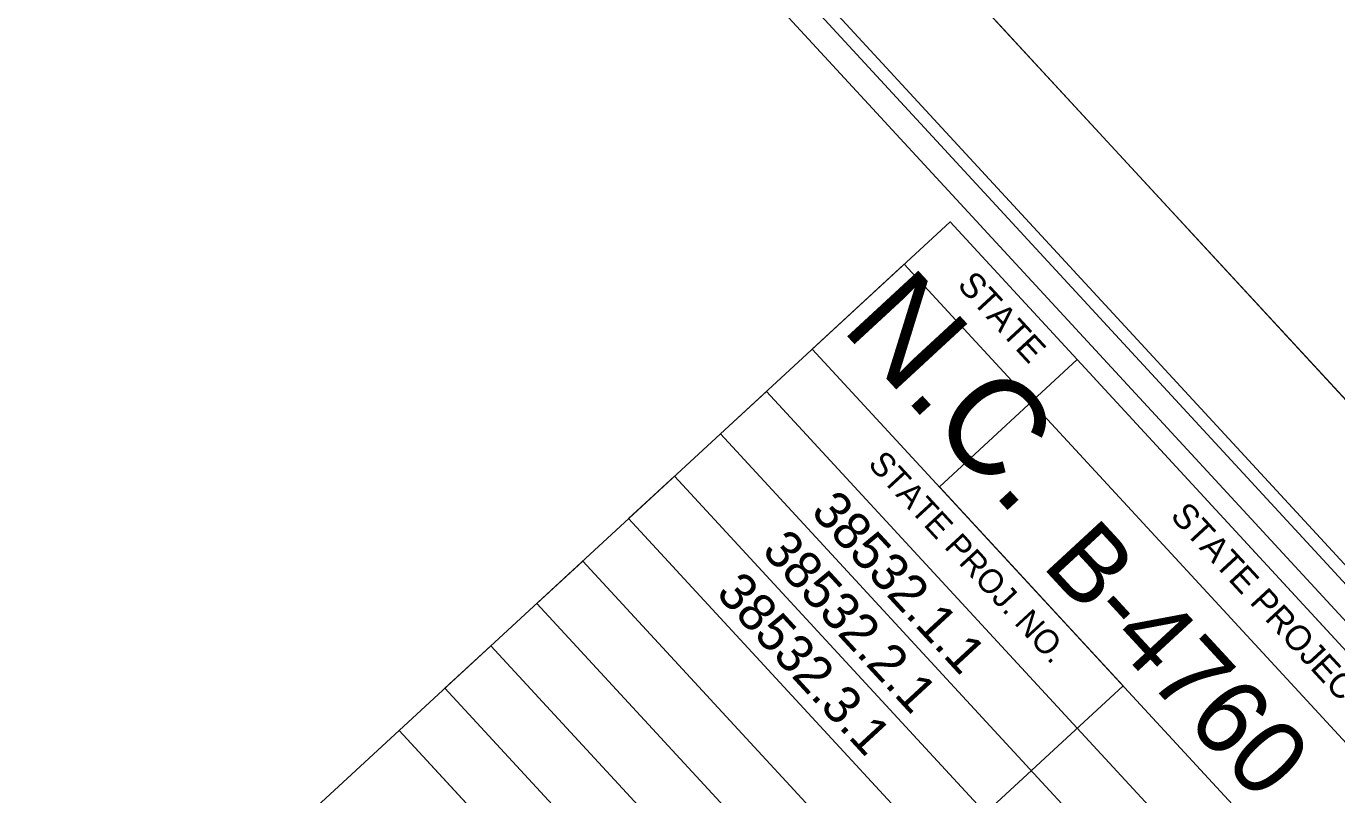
# Model space of a CAD drawing. Extents: x 1695041 to 1706254, y 786537 to 798223.
# Drawn here: x 1705012 to 1705798, y 794761 to 795222 of the extents above; entities that cross this region are included whole.
import ezdxf

# ---------------------------------------------------------------- set-up
doc = ezdxf.new("R2010")
doc.units = 0
for name, color, linetype in [('Old_Level_12', 7, 'Continuous'), ('Sheet Cutting Line CELL', 7, 'Continuous'), ('Sheet Data Field CELL', 7, 'Continuous'), ('Sheet Plot Border Inside CELL', 7, 'Continuous'), ('Sheet Plot Border Outside CELL', 7, 'Continuous'), ('Sheet Title CELL', 7, 'Continuous')]:
    doc.layers.add(name, color=color, linetype=linetype)

msp = doc.modelspace()

# ---------------------------------------------------------------- linework, layer by layer
at = {"layer": 'Old_Level_12'}
msp.add_lwpolyline([(1705795.09, 794193.47), (1705235.51, 794799.69), (1705053.77, 794631.93), (1705613.35, 794025.71)], close=True, dxfattribs=at)
at = {"layer": 'Sheet Cutting Line CELL'}
msp.add_line((1702826.93, 798222.79), (1706253.58, 794510.54), dxfattribs=at)
at = {"layer": 'Sheet Plot Border Inside CELL'}
msp.add_lwpolyline([(1700478.01, 796001.5), (1703869.05, 792327.83), (1706194.94, 794474.78), (1702803.9, 798148.45)], close=True, dxfattribs=at)
at = {"layer": 'Sheet Plot Border Outside CELL'}
msp.add_lwpolyline([(1706253.58, 794510.54), (1702826.93, 798222.79), (1700402.1, 795984.5), (1703828.75, 792272.26)], close=True, dxfattribs=at)
at = {"layer": 'Sheet Title CELL'}
for points in [[(1706143.56, 794519.16), (1703131.99, 797781.79)], [(1706122.34, 794520.04), (1703232.91, 797650.29)], [(1706125.75, 794498.7), (1705566.15, 795104.89), (1705235.51, 794799.69), (1705421.98, 794597.63), (1705669.98, 794826.55), (1705559.79, 794945.92), (1705642.48, 795022.25), (1705973.14, 794663.98)], [(1706043.09, 794422.39), (1705483.51, 795028.61), (1705538.62, 795079.48), (1706098.2, 794473.26)], [(1705987.95, 794371.5), (1705428.37, 794977.71), (1705455.93, 795003.15), (1706015.51, 794396.93)], [(1705932.87, 794320.65), (1705373.29, 794926.87), (1705400.82, 794952.28), (1705960.42, 794346.09)], [(1705877.73, 794269.75), (1705318.18, 794875.94), (1705345.73, 794901.43), (1705905.31, 794295.22)], [(1705822.62, 794218.88), (1705263.07, 794825.13), (1705290.6, 794850.54), (1705850.17, 794244.32)], [(1705235.51, 794799.69), (1705795.09, 794193.47)]]:
    msp.add_lwpolyline(points, dxfattribs=at)

# ---------------------------------------------------------------- texts
at = {"layer": 'Sheet Data Field CELL'}
for s, height, p in [('38532.1.1 ', 22.5, (1705482.01, 794930.44)), ('B-4760    ', 45, (1705620.57, 794898.65)), ('38532.2.1 ', 22.5, (1705452.62, 794906.99)), ('38532.3.1 ', 22.5, (1705425.1, 794881.58))]:
    msp.add_text(s, height=height, rotation=312.70907, dxfattribs=at).set_placement(p)
at = {"layer": 'Sheet Title CELL'}
for s, height, p in [('N.C.', 58.05, (1705500.14, 795040.89)), ('STATE', 14.999, (1705569.95, 795066.55)), ('STATE PROJ. NO.', 14.4, (1705516.4, 794959.14)), ('STATE PROJECT REFERENCE NO.', 14.9994, (1705697.81, 794927.98))]:
    msp.add_text(s, height=height, rotation=312.70907, dxfattribs=at).set_placement(p)

doc.saveas('drawing.dxf')
